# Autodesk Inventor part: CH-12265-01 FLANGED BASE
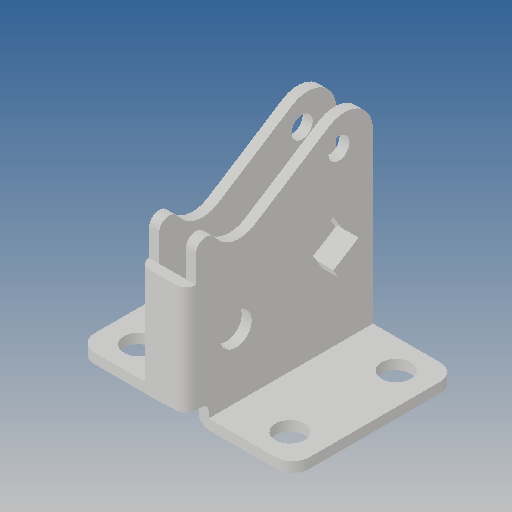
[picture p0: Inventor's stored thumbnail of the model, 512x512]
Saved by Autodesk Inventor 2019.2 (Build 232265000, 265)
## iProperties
Created: 2012-09
Part Number: CH-12265-01 FLANGED BASE
Material: Ogólny
Document SubType Name: Modeling
Designer: CADENGINEERING4
Density: 1 g/cm^3
Appearance: Domyślna
Author: CADENGINEERING4
Revision Number: ÈÎºÎ
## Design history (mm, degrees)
feature "Ô²½Ç4"
node "Bryła1"
